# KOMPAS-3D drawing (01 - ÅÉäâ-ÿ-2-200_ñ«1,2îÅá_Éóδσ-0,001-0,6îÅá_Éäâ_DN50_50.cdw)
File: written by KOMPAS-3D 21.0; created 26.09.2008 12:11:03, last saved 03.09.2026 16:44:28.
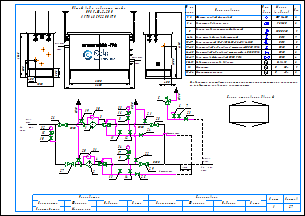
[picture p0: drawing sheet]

Sheets 1-2: A3, landscape

Document properties: Наименование: Макро:21; Автор: RaskoAdmin; Форматы листов документа: 2xA3; Полное имя файла: \\UR38nt01\Departments\КТО\КБ ПУРДГ\Заявки\Прайс-лист на типовые шкафы ГРПШ\ПРДГ_стандарт_20_03_2026\ПРДГ с РДГ(Н, В)\ПРДГ-Ш-2-200_до1,2МПа_Рвых-0,001-0,6МПа_РДГ_DN50_50.cdw

Title block, sheet 1: Наименование: Пункт учета газа / ПУГ-Ш-400-Р / ЛГТИ.485922.001ТУ; designation: ЛГТИ.03.4411141; sheet number: 1; Количество листов документа: 2; organisation: ООО "ЭЛЬСТЕР Газэлектроника"; Форматы листов документа: A3; stored path: C:\Рабочие документы\Компас\ПУГ\Схема.cdw; Разработал: Устинов; Проверил: Кошкин; Утвердил: Кошкин
Title block, sheet 2: sheet number: 2; stored path: D:\Рабочие документы\Заявки\ПУРДГ\ПУРДГ-ШУЭО-2-100-Р 4411220.cdw; designation, second copy: ЛГТИ.03.4411141-

Views: Вид 1, Вид 2
Referenced files: wcvoit.frw
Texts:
  Normal
  Вход
  газа
  PDI
  Выход
  Р=     кПа
  DN50
  DN20
  Импульс DN20
  ≥5DN
  HYSWLongFangSong
  № на
  схеме
  Усл.
  обозн.
  Марка
  (модель)
  Кол.
  Фильтр газовый фланцевый
  ФГ 16-50
  Регулятор давления газа
  РДГ-50
  Клапан предохранительный сбросной
  КПС DN20
  Кран шаровой газовый латунный
  DN15
  Кран кнопочный VE-РАСКО-НЗ-1,6-G1/2-М20
  Кран шаровой "под приварку" штуцерный DN20 PN16
  Кран шаровой "под приварку" штуцерный п/п DN20 PN16
  Кран шаровой фланцевый DN50 PN16
  Индикатор перепада давления
  Delta 15
  Манометр
  Манометр-напоромер
  0...     МПа
  0...     кПа
  Общий вид и габариты шкафа
  ПРДГ-Ш-2-200
  Выход газа
  Вход газа
  Схема открывания дверей
  Р=       МПа
  logo-rasko-ge.png
  Предприятие изготовитель может заменять комплектующие на аналогичные,
  не ухудшающие заявленных характеристик.
  Должность
  Конструктор
  Фамилия
  Подпись
  Дата
  Согласовано
  Максимкин
  Лист
  Листов
  POLYLINE_STYLE_0.18_RGB_0_0_0
  POLYLINE_STYLE_0.50_RGB_0_0_0
  POLYLINE_STYLE_0.34_RGB_0_0_0
  PHANTOM_RGB_0_0_0_SC_1_THICK_0.18
  K5LT_THIN_RGB_0_0_0_THICK_0.18
  K5LT32769_RGB_0_0_0_THICK_0.18
  K5LT12_RGB_0_0_0_SC_1_THICK_0.18
  K5LT_DASHED_RGB_0_0_0_SC_1_THICK_0.18
  ACISOTGL_RGB_0_0_0_SC_0.8_THICK_0.25
  CONTINUOUS_RGB_0_127_31_THICK_0.3
  CONTINUOUS_RGB_0_0_255_THICK_0.35
  CONTINUOUS_RGB_255_0_0_THICK_0.35
  POLYLINE_STYLE_0.25_RGB_0_0_0
  CONTINUOUS_RGB_0_0_0_THICK_0.5
  POLYLINE_STYLE_0.35_RGB_0_0_255
  CONTINUOUS_RGB_0_0_0_THICK_0.4
  CONTINUOUS_RGB_0_0_0_THICK_0.35
  Без оформления
Dimensions and other numbers on the sheet: 1; 2; 3; 4; 5; 10; 27; 28; 29; 23; 8; 12; 19; 20; 21; 22; 25; 24; 30; 31; 15; 16; 26; 6; 7; 11; 14; 13; 33; 1, 2; 3, 4; 6-14; 9; 15-17; 19-23; 24-25; 26-29; 30-31; 32; 33-34; 1000; 400; 1050; 500; 305; 2300; 4130; 1565; 2600; 17; 34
